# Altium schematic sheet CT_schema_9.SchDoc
size 274 x 160 mm
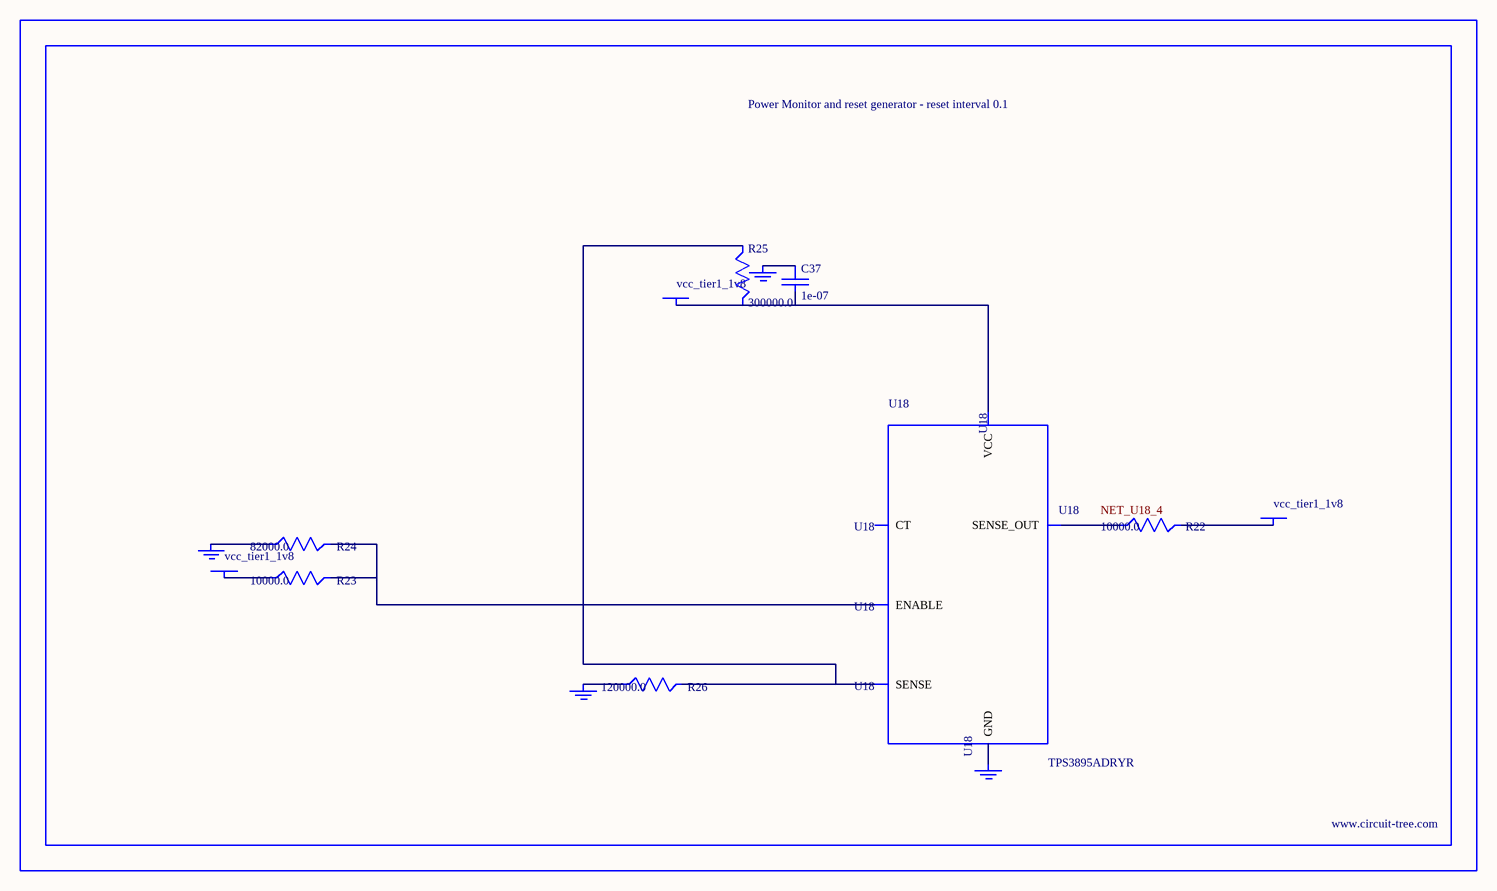
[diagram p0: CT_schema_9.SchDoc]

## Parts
BORDER8  (no value)
C37  1e-07  [C0402]
GND_INSTANCE_8_0  (no value)
GND_INSTANCE_8_1  (no value)
GND_INSTANCE_8_2  (no value)
GND_INSTANCE_8_3  (no value)
POWER_INSTANCE_8_0  vcc_tier1_1v8
POWER_INSTANCE_8_1  vcc_tier1_1v8
POWER_INSTANCE_8_2  vcc_tier1_1v8
R22  10000.0  [R0603]
R23  10000.0  [R0603]
R24  82000.0  [R0603]
R25  300000.0  [R0603]
R26  120000.0  [R0603]
U18  TPS3895ADRYR  [SON-6]

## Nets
NetC37_1: C37.1 GND_INSTANCE_8_2.0(GND)
NetC37_2: C37.2 POWER_INSTANCE_8_2.0(PWR) R25.2 U18.6(VCC)
NetGND_INSTANCE_8_0_0: GND_INSTANCE_8_0.0(GND) R24.1
NetGND_INSTANCE_8_1_0: GND_INSTANCE_8_1.0(GND) R26.1
NetGND_INSTANCE_8_3_0: GND_INSTANCE_8_3.0(GND) U18.2(GND)
NetPOWER_INSTANCE_8_0_0: POWER_INSTANCE_8_0.0(PWR) R23.1
NetPOWER_INSTANCE_8_1_0: POWER_INSTANCE_8_1.0(PWR) R22.2
NetR22_1: R22.1 U18.4(SENSE_OUT)
NetR23_2: R23.2 R24.2 U18.1(ENABLE)
NetR25_1: R25.1 R26.2 U18.3(SENSE)

Not connected (* = marked no-connect by the designer): U18 5(CT)

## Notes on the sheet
- Labels drawn without touching a wire or pin: NET_U18_4

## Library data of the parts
BORDER8 = BORDER_PAGE8
C37 = C0402C104K3RACTU
GND_INSTANCE_8_0-GND_INSTANCE_8_3 = GND
POWER_INSTANCE_8_0-POWER_INSTANCE_8_2 = PWR
R22 R23 = RC0603JR-0710KL
R24 = RC0603JR-0782KL
R25 = RC0603JR-07300KL
R26 = RC0603JR-07120KL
